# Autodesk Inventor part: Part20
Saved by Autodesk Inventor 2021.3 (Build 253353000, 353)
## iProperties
Created: 2022-08
Part Number: Part20
Material: Generic
Document SubType Name: Modeling
Designer: Administrator
Density: 1 g/cm^3
Appearance: Default
Author: Administrator
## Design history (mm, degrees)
feature "Cloche Petite"
body "Solid1"
